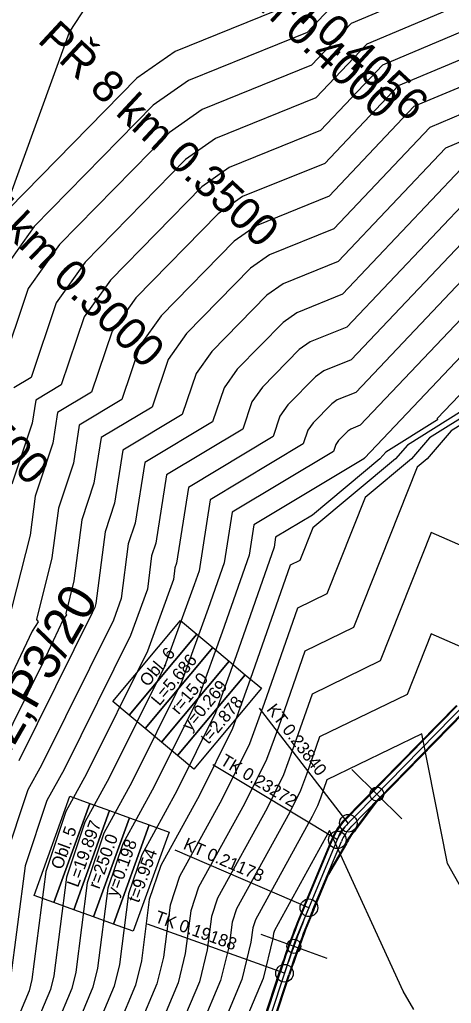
# Model space of a CAD drawing. Extents: x -549394 to -546608, y -1037055 to -1033629.
# Drawn here: x -548756.1 to -548633.3, y -1034201.2 to -1033921.5 of the extents above; entities that cross this region are included whole.
import ezdxf

# ---------------------------------------------------------------- set-up
doc = ezdxf.new("R2010")
doc.units = 0
for name, color, linetype in [('hlavni_vrst', 7, 'Continuous'), ('norm_vrst', 7, 'Continuous'), ('POLYGONY_SITUACE_PO', 7, 'Continuous'), ('u_sirka_0_5m', 7, 'Continuous'), ('x_navrh_C122', 7, 'Continuous'), ('x_osa_C122', 7, 'Continuous'), ('x_popis_oblouky_C122', 7, 'Continuous'), ('x_popis_pricne_rezy_C122', 7, 'Continuous'), ('x_popis_velky_C122', 7, 'Continuous')]:
    doc.layers.add(name, color=color, linetype=linetype)

msp = doc.modelspace()

# ---------------------------------------------------------------- linework, layer by layer
at = {"layer": 'hlavni_vrst'}
for p, q in [((-548628.37, -1033924.06), (-548652.86, -1033934.37)), ((-548652.86, -1033934.37), (-548670.52, -1033953.01)), ((-548670.52, -1033953.01), (-548696.49, -1033963.52)), ((-548696.49, -1033963.52), (-548704.26, -1033968.98)), ((-548630.48, -1033963.92), (-548664.24, -1033999.57)), ((-548704.26, -1033968.98), (-548730.27, -1033995.53)), ((-548608.09, -1033993.47), (-548657.97, -1034046.13)), ((-548730.27, -1033995.53), (-548737.72, -1034006)), ((-548664.24, -1033999.57), (-548677.27, -1034004.84)), ((-548677.27, -1034004.84), (-548681.16, -1034007.58)), ((-548737.72, -1034006), (-548744.24, -1034025.33)), ((-548681.16, -1034007.58), (-548694.21, -1034020.89)), ((-548694.21, -1034020.89), (-548697.94, -1034026.14)), ((-548744.24, -1034025.33), (-548751.51, -1034029.69)), ((-548697.94, -1034026.14), (-548701.21, -1034035.84)), ((-548751.51, -1034029.69), (-548752.53, -1034036.21)), ((-548752.53, -1034036.21), (-548758.32, -1034053.57)), ((-548701.21, -1034035.84), (-548720.49, -1034047.4)), ((-548720.49, -1034047.4), (-548723.2, -1034064.67)), ((-548658.19, -1034046.35), (-548689.46, -1034065.1)), ((-548658.17, -1034046.29), (-548658.19, -1034046.35)), ((-548658.15, -1034046.26), (-548658.17, -1034046.29)), ((-548658.07, -1034046.18), (-548658.15, -1034046.26)), ((-548658.05, -1034046.16), (-548658.07, -1034046.18)), ((-548657.97, -1034046.13), (-548658.05, -1034046.16)), ((-548723.2, -1034064.67), (-548725.16, -1034070.55)), ((-548689.46, -1034065.1), (-548690.82, -1034073.74)), ((-548638.98, -1034067.36), (-548653.49, -1034103.86)), ((-548611.26, -1034079.53), (-548638.98, -1034067.36)), ((-548725.16, -1034070.55), (-548727.15, -1034086.06)), ((-548690.82, -1034073.74), (-548698.45, -1034095.69)), ((-548727.15, -1034086.06), (-548729.39, -1034092.21)), ((-548729.39, -1034092.21), (-548749.87, -1034133.46)), ((-548698.45, -1034095.69), (-548705.2, -1034114.25)), ((-548653.49, -1034103.86), (-548672.9, -1034113.25)), ((-548705.2, -1034114.25), (-548717.77, -1034139.57)), ((-548672.9, -1034113.25), (-548678.51, -1034129.39)), ((-548678.51, -1034129.39), (-548681.01, -1034136.28)), ((-548749.87, -1034133.46), (-548753.73, -1034140.48)), ((-548681.01, -1034136.28), (-548685.68, -1034145.68)), ((-548717.77, -1034139.57), (-548726.75, -1034155.89)), ((-548753.73, -1034140.48), (-548760.4, -1034160.49)), ((-548685.68, -1034145.68), (-548699.78, -1034171.31)), ((-548726.75, -1034155.89), (-548730.96, -1034168.51)), ((-548730.96, -1034168.51), (-548733.9, -1034191.27)), ((-548699.78, -1034171.31), (-548701.52, -1034176.54)), ((-548701.52, -1034176.54), (-548702.74, -1034185.97)), ((-548702.74, -1034185.97), (-548704.96, -1034195.08)), ((-548733.9, -1034191.27), (-548735.22, -1034196.67)), ((-548704.96, -1034195.08), (-548724.74, -1034242.04)), ((-548735.22, -1034196.67), (-548746.95, -1034224.54))]:
    msp.add_line(p, q, dxfattribs=at)
at = {"layer": 'norm_vrst'}
for p, q in [((-548633.56, -1033910.66), (-548661.82, -1033922.55)), ((-548675.54, -1033915.76), (-548711.87, -1033930.47)), ((-548741.85, -1033924.97), (-548736.86, -1033917.29)), ((-548666.3, -1033916.64), (-548674.29, -1033925.07)), ((-548630.97, -1033917.36), (-548657.34, -1033928.46)), ((-548661.82, -1033922.55), (-548673.03, -1033934.39)), ((-548759.67, -1033974.12), (-548741.85, -1033924.97)), ((-548674.29, -1033925.07), (-548708.03, -1033938.73)), ((-548657.34, -1033928.46), (-548671.78, -1033943.7)), ((-548711.87, -1033930.47), (-548722.73, -1033938.1)), ((-548625.78, -1033930.77), (-548648.39, -1033940.28)), ((-548673.03, -1033934.39), (-548704.18, -1033946.99)), ((-548722.73, -1033938.1), (-548759.11, -1033975.23)), ((-548623.19, -1033937.47), (-548643.91, -1033946.19)), ((-548708.03, -1033938.73), (-548718.11, -1033945.82)), ((-548648.39, -1033940.28), (-548669.27, -1033962.32)), ((-548671.78, -1033943.7), (-548700.34, -1033955.26)), ((-548620.59, -1033944.17), (-548639.43, -1033952.1)), ((-548718.11, -1033945.82), (-548751.9, -1033980.31)), ((-548643.91, -1033946.19), (-548668.01, -1033971.63)), ((-548704.18, -1033946.99), (-548713.49, -1033953.54)), ((-548639.43, -1033952.1), (-548666.75, -1033980.95)), ((-548618, -1033950.87), (-548634.96, -1033958.01)), ((-548713.49, -1033953.54), (-548744.69, -1033985.38)), ((-548700.34, -1033955.26), (-548708.87, -1033961.26)), ((-548634.96, -1033958.01), (-548665.5, -1033990.26)), ((-548708.87, -1033961.26), (-548737.48, -1033990.45)), ((-548669.27, -1033962.32), (-548692.65, -1033971.79)), ((-548692.65, -1033971.79), (-548699.64, -1033976.7)), ((-548668.01, -1033971.63), (-548688.8, -1033980.05)), ((-548626, -1033969.83), (-548662.99, -1034008.88)), ((-548699.64, -1033976.7), (-548723.05, -1034000.6)), ((-548621.52, -1033975.74), (-548661.73, -1034018.19)), ((-548751.9, -1033980.31), (-548761.58, -1033993.91)), ((-548688.8, -1033980.05), (-548695.02, -1033984.42)), ((-548666.75, -1033980.95), (-548684.96, -1033988.31)), ((-548617.05, -1033981.65), (-548660.48, -1034027.51)), ((-548744.69, -1033985.38), (-548753.63, -1033997.94)), ((-548695.02, -1033984.42), (-548715.84, -1034005.67)), ((-548684.96, -1033988.31), (-548690.4, -1033992.14)), ((-548612.57, -1033987.56), (-548659.22, -1034036.82)), ((-548737.48, -1033990.45), (-548745.67, -1034001.97)), ((-548665.5, -1033990.26), (-548681.11, -1033996.58)), ((-548690.4, -1033992.14), (-548708.63, -1034010.74)), ((-548681.11, -1033996.58), (-548685.78, -1033999.86)), ((-548753.63, -1033997.94), (-548761.45, -1034021.12)), ((-548685.78, -1033999.86), (-548701.42, -1034015.82)), ((-548603.61, -1033999.38), (-548637.27, -1034034.91)), ((-548745.67, -1034001.97), (-548752.84, -1034023.23)), ((-548723.05, -1034000.6), (-548729.76, -1034010.03)), ((-548715.84, -1034005.67), (-548721.81, -1034014.06)), ((-548729.76, -1034010.03), (-548735.63, -1034027.43)), ((-548708.63, -1034010.74), (-548713.85, -1034018.09)), ((-548662.99, -1034008.88), (-548673.42, -1034013.11)), ((-548721.81, -1034014.06), (-548727.03, -1034029.53)), ((-548673.42, -1034013.11), (-548676.54, -1034015.3)), ((-548595.73, -1034012.97), (-548639.5, -1034040.41)), ((-548701.42, -1034015.82), (-548705.9, -1034022.11)), ((-548676.54, -1034015.3), (-548686.99, -1034025.96)), ((-548598.23, -1034016.4), (-548633.3, -1034038.39)), ((-548713.85, -1034018.09), (-548718.42, -1034031.63)), ((-548661.73, -1034018.19), (-548669.58, -1034021.37)), ((-548705.9, -1034022.11), (-548709.82, -1034033.74)), ((-548669.58, -1034021.37), (-548671.92, -1034023.02)), ((-548752.84, -1034023.23), (-548757.71, -1034026.15)), ((-548671.92, -1034023.02), (-548679.78, -1034031.04)), ((-548615.89, -1034023.73), (-548645.71, -1034042.43)), ((-548735.63, -1034027.43), (-548745.31, -1034033.23)), ((-548686.99, -1034025.96), (-548689.99, -1034030.17)), ((-548660.48, -1034027.51), (-548665.73, -1034029.63)), ((-548727.03, -1034029.53), (-548739.1, -1034036.77)), ((-548689.99, -1034030.17), (-548692.61, -1034037.94)), ((-548667.31, -1034030.74), (-548672.57, -1034036.11)), ((-548665.73, -1034029.63), (-548667.31, -1034030.74)), ((-548745.31, -1034033.23), (-548746.67, -1034041.9)), ((-548718.42, -1034031.63), (-548732.9, -1034040.31)), ((-548679.78, -1034031.04), (-548682.03, -1034034.2)), ((-548709.82, -1034033.74), (-548726.69, -1034043.86)), ((-548682.03, -1034034.2), (-548684, -1034040.04)), ((-548672.57, -1034036.11), (-548674.08, -1034038.23)), ((-548637.23, -1034035.25), (-548651.91, -1034044.45)), ((-548637.27, -1034034.91), (-548637.23, -1034035.25)), ((-548739.1, -1034036.77), (-548740.8, -1034047.59)), ((-548692.61, -1034037.94), (-548714.28, -1034050.94)), ((-548674.08, -1034038.23), (-548675.4, -1034042.14)), ((-548662.69, -1034038.46), (-548665.36, -1034041.18)), ((-548661.89, -1034037.9), (-548662.69, -1034038.46)), ((-548659.22, -1034036.82), (-548661.89, -1034037.9)), ((-548633.3, -1034038.39), (-548640.18, -1034046.38)), ((-548746.67, -1034041.9), (-548751.69, -1034056.96)), ((-548732.9, -1034040.31), (-548734.93, -1034053.28)), ((-548684, -1034040.04), (-548708.08, -1034054.48)), ((-548665.36, -1034041.18), (-548666.12, -1034042.26)), ((-548639.5, -1034040.41), (-548644.65, -1034046.39)), ((-548726.69, -1034043.86), (-548729.07, -1034058.98)), ((-548675.4, -1034042.14), (-548701.87, -1034058.02)), ((-548666.79, -1034044.25), (-548695.67, -1034061.56)), ((-548666.12, -1034042.26), (-548666.79, -1034044.25)), ((-548651.91, -1034044.45), (-548653.59, -1034046.4)), ((-548645.71, -1034042.43), (-548649.12, -1034046.4)), ((-548740.8, -1034047.59), (-548745.06, -1034060.36)), ((-548653.59, -1034046.4), (-548672.74, -1034062.34)), ((-548649.12, -1034046.4), (-548672.65, -1034065.98)), ((-548644.65, -1034046.39), (-548657.81, -1034057.34)), ((-548640.18, -1034046.38), (-548642.98, -1034048.71)), ((-548642.98, -1034048.71), (-548661.11, -1034094.32)), ((-548734.93, -1034053.28), (-548738.43, -1034063.75)), ((-548714.28, -1034050.94), (-548717.33, -1034070.36)), ((-548708.08, -1034054.48), (-548711.47, -1034076.05)), ((-548751.69, -1034056.96), (-548753.11, -1034068.04)), ((-548701.87, -1034058.02), (-548705.05, -1034078.25)), ((-548657.81, -1034057.34), (-548668.72, -1034084.78)), ((-548745.06, -1034060.36), (-548746.88, -1034074.54)), ((-548729.07, -1034058.98), (-548731.79, -1034067.15)), ((-548695.67, -1034061.56), (-548697.94, -1034075.99)), ((-548738.43, -1034063.75), (-548740.64, -1034081.04)), ((-548672.74, -1034062.34), (-548683.26, -1034068.64)), ((-548731.79, -1034067.15), (-548734.41, -1034087.54)), ((-548672.65, -1034065.98), (-548676.34, -1034075.24)), ((-548753.11, -1034068.04), (-548759.59, -1034093.8)), ((-548683.26, -1034068.64), (-548683.71, -1034071.48)), ((-548717.33, -1034070.36), (-548718.53, -1034073.94)), ((-548683.71, -1034071.48), (-548694.46, -1034102.43)), ((-548746.88, -1034074.54), (-548751.29, -1034092.07)), ((-548718.53, -1034073.94), (-548719.74, -1034083.4)), ((-548676.34, -1034075.24), (-548679.16, -1034076.61)), ((-548711.89, -1034077.34), (-548712.33, -1034080.73)), ((-548711.47, -1034076.05), (-548711.89, -1034077.34)), ((-548705.05, -1034078.25), (-548706.43, -1034082.21)), ((-548697.94, -1034075.99), (-548702.44, -1034088.95)), ((-548679.16, -1034076.61), (-548690.47, -1034109.17)), ((-548740.64, -1034081.04), (-548742.98, -1034090.34)), ((-548712.33, -1034080.73), (-548719.72, -1034101.03)), ((-548719.74, -1034083.4), (-548724.55, -1034096.62)), ((-548706.43, -1034082.21), (-548714.88, -1034105.43)), ((-548668.72, -1034084.78), (-548677.07, -1034088.82)), ((-548734.76, -1034088.81), (-548735.41, -1034090.19)), ((-548734.65, -1034088.65), (-548734.76, -1034088.81)), ((-548734.41, -1034087.54), (-548734.68, -1034088.61)), ((-548734.68, -1034088.61), (-548734.65, -1034088.65)), ((-548702.44, -1034088.95), (-548710.04, -1034109.84)), ((-548677.07, -1034088.82), (-548686.48, -1034115.91)), ((-548735.41, -1034090.19), (-548756.29, -1034132.24)), ((-548751.29, -1034092.07), (-548750.8, -1034092.76)), ((-548743.65, -1034092.09), (-548749.37, -1034104.15)), ((-548742.73, -1034090.71), (-548743.65, -1034092.09)), ((-548742.98, -1034090.34), (-548742.73, -1034090.71)), ((-548750.8, -1034092.76), (-548752.55, -1034095.38)), ((-548661.11, -1034094.32), (-548674.98, -1034101.04)), ((-548752.55, -1034095.38), (-548763.32, -1034118.11)), ((-548724.55, -1034096.62), (-548743.45, -1034134.69)), ((-548639, -1034096.11), (-548645.87, -1034113.4)), ((-548621.22, -1034103.91), (-548639, -1034096.11)), ((-548719.72, -1034101.03), (-548737.03, -1034135.91)), ((-548694.46, -1034102.43), (-548700.36, -1034118.65)), ((-548674.98, -1034101.04), (-548682.49, -1034122.65)), ((-548749.37, -1034104.15), (-548762.71, -1034131.02)), ((-548714.88, -1034105.43), (-548730.61, -1034137.13)), ((-548690.47, -1034109.17), (-548695.53, -1034123.06)), ((-548710.04, -1034109.84), (-548724.19, -1034138.35)), ((-548645.87, -1034113.4), (-548670.81, -1034125.46)), ((-548686.48, -1034115.91), (-548690.69, -1034127.47)), ((-548700.36, -1034118.65), (-548711.35, -1034140.79)), ((-548695.53, -1034123.06), (-548704.93, -1034142.01)), ((-548682.49, -1034122.65), (-548685.85, -1034131.87)), ((-548670.81, -1034125.46), (-548674.52, -1034136.13)), ((-548641.66, -1034124.58), (-548668.72, -1034137.68)), ((-548634.4, -1034161.46), (-548641.66, -1034124.58)), ((-548690.69, -1034127.47), (-548698.52, -1034143.23)), ((-548685.85, -1034131.87), (-548692.1, -1034144.46)), ((-548743.45, -1034134.69), (-548748.34, -1034143.56)), ((-548737.03, -1034135.91), (-548742.94, -1034146.65)), ((-548730.61, -1034137.13), (-548737.54, -1034149.73)), ((-548674.52, -1034136.13), (-548676.17, -1034140.69)), ((-548724.19, -1034138.35), (-548732.15, -1034152.81)), ((-548668.72, -1034137.68), (-548670.53, -1034142.88)), ((-548711.35, -1034140.79), (-548721.36, -1034158.98)), ((-548704.93, -1034142.01), (-548715.96, -1034162.06)), ((-548676.17, -1034140.69), (-548679.26, -1034146.9)), ((-548748.34, -1034143.56), (-548754.51, -1034162.09)), ((-548698.52, -1034143.23), (-548710.57, -1034165.14)), ((-548692.1, -1034144.46), (-548705.17, -1034168.22)), ((-548671.34, -1034145.09), (-548672.84, -1034148.12)), ((-548670.53, -1034142.88), (-548671.34, -1034145.09)), ((-548742.94, -1034146.65), (-548748.62, -1034163.7)), ((-548679.26, -1034146.9), (-548694.38, -1034174.39)), ((-548672.84, -1034148.12), (-548688.99, -1034177.47)), ((-548737.54, -1034149.73), (-548742.74, -1034165.3)), ((-548732.15, -1034152.81), (-548736.85, -1034166.91)), ((-548667.92, -1034152.07), (-548683.59, -1034180.56)), ((-548647.02, -1034197.79), (-548667.92, -1034152.07)), ((-548721.36, -1034158.98), (-548725.07, -1034170.12)), ((-548754.51, -1034162.09), (-548758.83, -1034195.5)), ((-548715.96, -1034162.06), (-548719.19, -1034171.72)), ((-548617.38, -1034191.77), (-548634.4, -1034161.46)), ((-548748.62, -1034163.7), (-548752.59, -1034194.44)), ((-548710.57, -1034165.14), (-548713.3, -1034173.33)), ((-548742.74, -1034165.3), (-548746.36, -1034193.39)), ((-548736.85, -1034166.91), (-548740.13, -1034192.33)), ((-548725.07, -1034170.12), (-548727.67, -1034190.21)), ((-548705.17, -1034168.22), (-548707.41, -1034174.93)), ((-548719.19, -1034171.72), (-548721.44, -1034189.15)), ((-548713.3, -1034173.33), (-548715.2, -1034188.09)), ((-548707.41, -1034174.93), (-548708.97, -1034187.03)), ((-548694.38, -1034174.39), (-548695.63, -1034178.14)), ((-548695.63, -1034178.14), (-548696.51, -1034184.91)), ((-548688.99, -1034177.47), (-548689.75, -1034179.75)), ((-548689.75, -1034179.75), (-548690.28, -1034183.85)), ((-548683.86, -1034181.35), (-548684.05, -1034182.79)), ((-548683.59, -1034180.56), (-548683.86, -1034181.35)), ((-548690.28, -1034183.85), (-548692.86, -1034194.44)), ((-548684.05, -1034182.79), (-548686.81, -1034194.12)), ((-548708.97, -1034187.03), (-548711.01, -1034195.4)), ((-548696.51, -1034184.91), (-548698.91, -1034194.76)), ((-548727.67, -1034190.21), (-548729.17, -1034196.35)), ((-548721.44, -1034189.15), (-548723.11, -1034196.04)), ((-548715.2, -1034188.09), (-548717.06, -1034195.72)), ((-548740.13, -1034192.33), (-548741.27, -1034196.99)), ((-548752.59, -1034194.44), (-548753.37, -1034197.63)), ((-548746.36, -1034193.39), (-548747.32, -1034197.31)), ((-548717.06, -1034195.72), (-548733.62, -1034235.04)), ((-548711.01, -1034195.4), (-548729.18, -1034238.54)), ((-548698.91, -1034194.76), (-548720.29, -1034245.54)), ((-548692.86, -1034194.44), (-548715.85, -1034249.04)), ((-548686.81, -1034194.12), (-548711.41, -1034252.54)), ((-548753.37, -1034197.63), (-548760.28, -1034214.05)), ((-548747.32, -1034197.31), (-548755.84, -1034217.55)), ((-548741.27, -1034196.99), (-548751.4, -1034221.04)), ((-548729.17, -1034196.35), (-548742.51, -1034228.04)), ((-548723.11, -1034196.04), (-548738.07, -1034231.54)), ((-548643.93, -1034203.01), (-548647.02, -1034197.79))]:
    msp.add_line(p, q, dxfattribs=at)
at = {"layer": 'POLYGONY_SITUACE_PO'}
for centre in [(-548662.59, -1034150.01), (-548665.71, -1034154.72), (-548673.79, -1034174.04), (-548680.73, -1034192.68)]:
    msp.add_circle(centre, 2.5, dxfattribs=at)
at = {"layer": 'u_sirka_0_5m'}
for centre in [(-548654.47, -1034141.73), (-548678.08, -1034185.01)]:
    msp.add_circle(centre, 2, dxfattribs=at)
at = {"layer": 'x_navrh_C122'}
for p, q in [((-548663.48, -1034149.14), (-548631.66, -1034116.66)), ((-548661.7, -1034150.89), (-548629.88, -1034118.41)), ((-548660.72, -1034151.84), (-548654.7, -1034143.74)), ((-548660.53, -1034152.01), (-548654.51, -1034143.91)), ((-548674.95, -1034173.55), (-548666.87, -1034154.24)), ((-548672.64, -1034174.52), (-548664.56, -1034155.2)), ((-548663.3, -1034155.73), (-548668.42, -1034164.43)), ((-548663.07, -1034155.84), (-548668.19, -1034164.54)), ((-548696.56, -1034236.98), (-548681.92, -1034192.29)), ((-548694.18, -1034237.76), (-548679.54, -1034193.07))]:
    msp.add_line(p, q, dxfattribs=at)
for points in [[(-548663.66, -1034148.96), (-548631.84, -1034116.49)], [(-548654.51, -1034143.91), (-548629.7, -1034118.59)], [(-548675.18, -1034173.46), (-548667.1, -1034154.14)], [(-548672.41, -1034174.62), (-548668.19, -1034164.54)], [(-548696.8, -1034236.9), (-548682.16, -1034192.21)], [(-548693.94, -1034237.83), (-548679.31, -1034193.15)]]:
    msp.add_lwpolyline(points, dxfattribs=at)
for centre, radius, start, end in [((-548651.88, -1034160.51), 16.5, 135.5825, 157.3027), ((-548651.88, -1034160.51), 16.25, 135.5825, 157.3027), ((-548651.88, -1034160.51), 13.75, 135.5825, 157.3027), ((-548651.88, -1034160.51), 12.38, 135.5825, 157.3027), ((-548651.88, -1034160.51), 12.13, 135.5024, 157.3828), ((-548443.15, -1034270.5), 251.5, 157.3027, 161.8627), ((-548443.15, -1034270.5), 251.25, 157.3027, 161.8627), ((-548443.15, -1034270.5), 248.75, 157.3027, 161.8627), ((-548443.15, -1034270.5), 248.5, 157.3027, 161.8627)]:
    msp.add_arc(centre, radius, start, end, dxfattribs=at)
at = {"layer": 'x_osa_C122'}
msp.add_lwpolyline([(-548717.69, -1034296.78), (-548699.62, -1034250.33), (-548699.62, -1034250.33), (-548677.63, -1034183.22), (-548677.63, -1034183.22), (-548677.63, -1034183.22), (-548664.6, -1034152.07), (-548606, -1034092.26), (-548545.79, -1034027.23)], dxfattribs=at)
for centre, radius, start, end in [((-548651.88, -1034160.51), 15, 135.5825, 157.3027), ((-548443.15, -1034270.5), 250, 157.3027, 161.8627)]:
    msp.add_arc(centre, radius, start, end, dxfattribs=at)
at = {"layer": 'x_popis_oblouky_C122'}
for points in [[(-548729.54, -1034115.38), (-548710.29, -1034092.37), (-548705.69, -1034096.22), (-548724.94, -1034119.23)], [(-548724.94, -1034119.23), (-548705.69, -1034096.22), (-548701.09, -1034100.07), (-548720.34, -1034123.08)], [(-548720.34, -1034123.08), (-548701.09, -1034100.07), (-548696.48, -1034103.92), (-548715.73, -1034126.93)], [(-548715.73, -1034126.93), (-548696.48, -1034103.92), (-548691.88, -1034107.77), (-548711.13, -1034130.78)], [(-548711.13, -1034130.78), (-548691.88, -1034107.77), (-548687.28, -1034111.62), (-548706.53, -1034134.63)], [(-548751.98, -1034170.54), (-548741.77, -1034142.33), (-548736.13, -1034144.37), (-548746.34, -1034172.58)], [(-548746.34, -1034172.58), (-548736.13, -1034144.37), (-548730.49, -1034146.42), (-548740.7, -1034174.63)], [(-548740.7, -1034174.63), (-548730.49, -1034146.42), (-548724.85, -1034148.46), (-548735.06, -1034176.67)], [(-548735.06, -1034176.67), (-548724.85, -1034148.46), (-548719.2, -1034150.5), (-548729.41, -1034178.71)], [(-548729.41, -1034178.71), (-548719.2, -1034150.5), (-548713.56, -1034152.54), (-548723.77, -1034180.75)]]:
    msp.add_lwpolyline(points, close=True, dxfattribs=at)
for points in [[(-548662.59, -1034150.01), (-548687.87, -1034117.26)], [(-548665.71, -1034154.72), (-548701.16, -1034133.38)], [(-548673.79, -1034174.04), (-548711.79, -1034157.66)], [(-548680.73, -1034192.68), (-548719.66, -1034178.67)]]:
    msp.add_lwpolyline(points, dxfattribs=at)
at = {"layer": 'x_popis_pricne_rezy_C122'}
for points in [[(-548661.62, -1034134.73), (-548654.47, -1034141.73), (-548647.33, -1034148.73)], [(-548687.48, -1034181.59), (-548678.08, -1034185.01), (-548668.68, -1034188.43)]]:
    msp.add_lwpolyline(points, dxfattribs=at)

# ---------------------------------------------------------------- texts
at = {"layer": 'x_popis_oblouky_C122'}
for s, rotation, p in [('Obl. 6', 50.1081, (-548719.62, -1034111.4)), ('L=5.686', 50.1081, (-548716.33, -1034116.82)), ('r=15.0', 50.1081, (-548710.81, -1034119.31)), ('y=0.269', 50.1081, (-548707.52, -1034124.04)), ('t=2.878', 50.1081, (-548702.35, -1034127.75)), ('KT 0.23840', 307.6726, (-548686, -1034117.71)), ('TK 0.23272', 328.9473, (-548699.29, -1034133.1)), ('Obl. 5', 70.1278, (-548744.03, -1034163.41)), ('L=19.897', 70.1278, (-548739.47, -1034168.47)), ('r=250.0', 70.1278, (-548733.44, -1034168.92)), ('y=0.198', 70.1278, (-548728.33, -1034171.14)), ('KT 0.21178', 336.6865, (-548709.79, -1034157.21)), ('t=9.954', 70.1278, (-548722.2, -1034172.86)), ('TK 0.19188', 340.2126, (-548717.88, -1034178.03))]:
    msp.add_text(s, height=3.5, rotation=rotation, dxfattribs=at).set_placement(p)
at = {"layer": 'x_popis_pricne_rezy_C122'}
for s, rotation, p in [('PŘ 10 km 0.4056', 317.205, (-548713.82, -1033887.18)), ('PŘ 9 km 0.4000', 317.205, (-548717.59, -1033891.25)), ('PŘ 8 km 0.3500', 317.0982, (-548751.3, -1033927.63)), ('PŘ 7 km 0.3000', 315.9523, (-548782.83, -1033960.62)), ('PŘ 6 km 0.2500', 315.5825, (-548815.16, -1033993.6))]:
    msp.add_text(s, height=9.0627, rotation=rotation, dxfattribs=at).set_placement(p)
at = {"layer": 'x_popis_velky_C122'}
msp.add_text('C122,P3/20', height=10.5, rotation=60.1062, dxfattribs=at).set_placement((-548770.49, -1034150.57))

doc.saveas('drawing.dxf')
